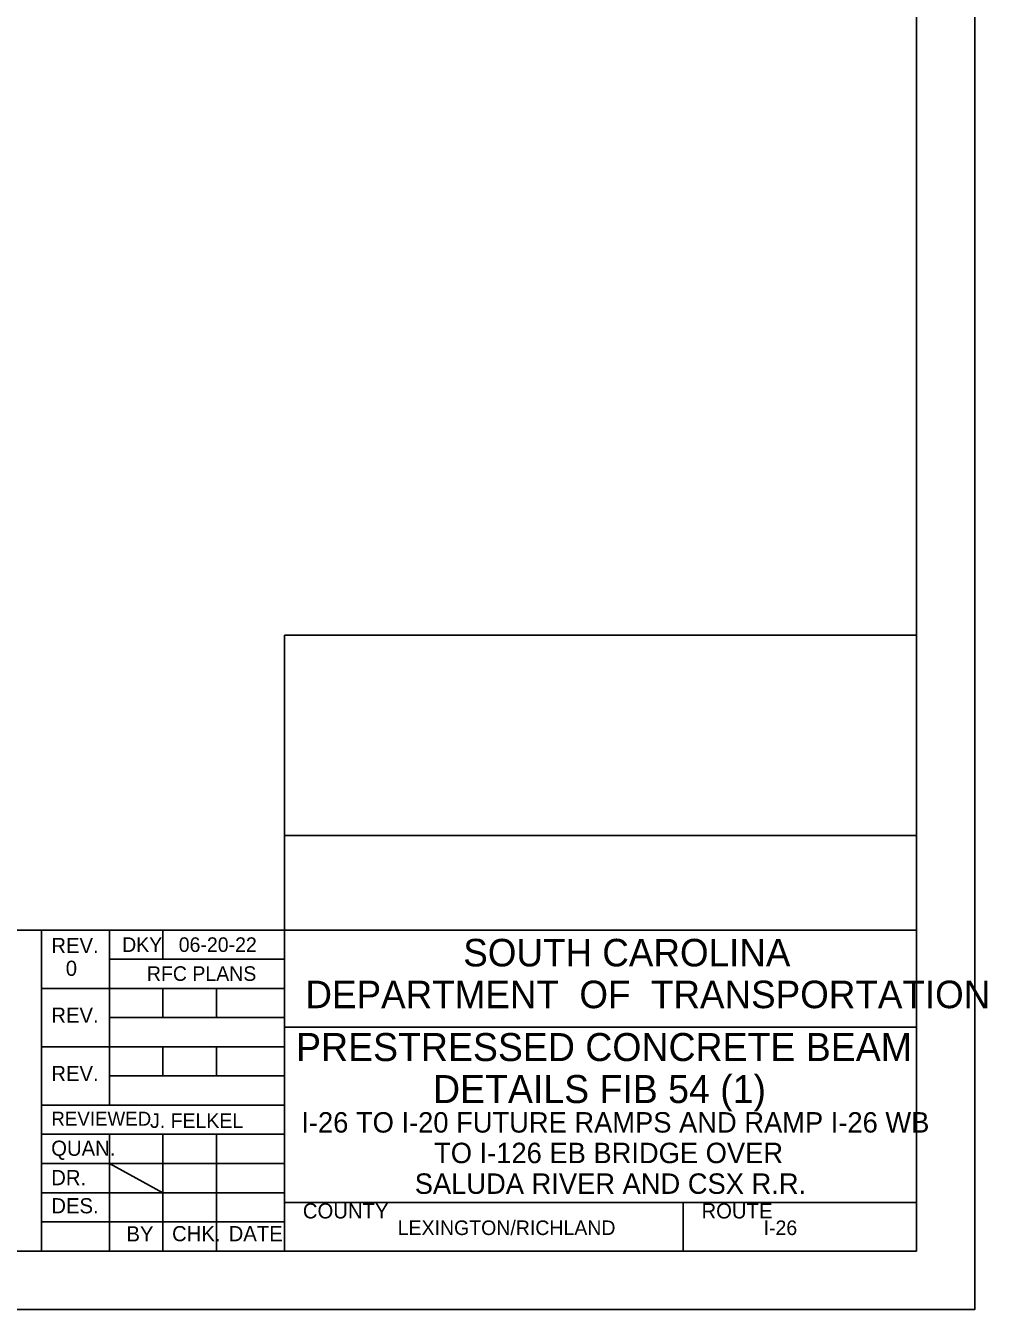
# Model space of a CAD drawing. Extents: x -55.6 to -19.5, y -5.1 to 16.9.
# Drawn here: x -27.72 to -19.48, y -5.09 to 5.91 of the extents above; entities that cross this region are included whole.
import ezdxf

# ---------------------------------------------------------------- set-up
doc = ezdxf.new("R2010")
doc.units = 0
for name, color, linetype in [('BR_BORDER LINES', 7, 'Continuous'), ('BR_TEXT', 7, 'Continuous'), ('Level 31', 7, 'Continuous')]:
    doc.layers.add(name, color=color, linetype=linetype)

msp = doc.modelspace()

# ---------------------------------------------------------------- linework, layer by layer
at = {"layer": 'BR_BORDER LINES'}
for p, q in [((-20.084, -4.592), (-20.084, 16.408)), ((-25.501, -4.592), (-25.501, 0.685)), ((-25.501, 0.685), (-20.084, 0.685)), ((-25.501, -1.03), (-20.084, -1.03)), ((-32.95, -1.842), (-27.584, -1.842)), ((-27.584, -4.592), (-27.584, -1.842)), ((-27.584, -1.842), (-20.084, -1.842)), ((-27.001, -1.842), (-27.001, -3.342)), ((-26.543, -2.092), (-26.543, -1.842)), ((-27.001, -2.092), (-25.501, -2.092)), ((-27.584, -2.342), (-25.501, -2.342)), ((-26.543, -2.592), (-26.543, -2.342)), ((-26.084, -2.592), (-26.084, -2.342)), ((-27.001, -2.592), (-25.501, -2.592)), ((-25.501, -2.675), (-25.501, -2.675)), ((-25.501, -2.675), (-20.084, -2.675)), ((-27.584, -2.842), (-25.501, -2.842)), ((-26.543, -3.092), (-26.543, -2.842)), ((-26.084, -3.092), (-26.084, -2.842)), ((-27.001, -3.092), (-25.501, -3.092)), ((-27.584, -3.342), (-25.501, -3.342)), ((-27.584, -3.592), (-25.501, -3.592)), ((-27.001, -3.592), (-27.001, -4.592)), ((-26.543, -3.592), (-26.543, -4.592)), ((-26.084, -3.592), (-26.084, -4.592)), ((-27.584, -3.842), (-25.501, -3.842)), ((-27.584, -4.092), (-25.501, -4.092)), ((-25.501, -4.175), (-20.084, -4.175)), ((-25.403, -4.175), (-20.084, -4.175)), ((-22.084, -4.592), (-22.084, -4.175)), ((-27.584, -4.342), (-25.501, -4.342)), ((-53.75, -4.592), (-20.084, -4.592))]:
    msp.add_line(p, q, dxfattribs=at)
at = {"layer": 'Level 31'}
for p, q in [((-22.792, -3.115), (-22.792, -3.115)), ((-27.001, -3.842), (-26.543, -4.092))]:
    msp.add_line(p, q, dxfattribs=at)
msp.add_lwpolyline([(-55.583, -5.092), (-19.583, -5.092), (-19.583, 16.908), (-55.583, 16.908)], close=True, dxfattribs=at)

# ---------------------------------------------------------------- texts
at = {"layer": 'BR_TEXT'}
for s, height, p in [('REV.', 0.13, (-27.5, -2.039)), ('DKY', 0.125, (-26.893, -2.029)), ('06-20-22', 0.125, (-26.408, -2.029)), ('SOUTH CAROLINA', 0.23587, (-23.969, -2.153)), ('0', 0.13, (-27.376, -2.234)), ('RFC PLANS', 0.125, (-26.681, -2.277)), ('DEPARTMENT  OF  TRANSPORTATION', 0.23587, (-25.322, -2.511)), ('REV.', 0.13, (-27.5, -2.636)), ('PRESTRESSED CONCRETE BEAM', 0.24, (-25.402, -2.964)), ('REV.', 0.13, (-27.5, -3.136)), ('DETAILS FIB 54 (1)', 0.24, (-24.228, -3.324)), ('REVIEWED', 0.12, (-27.5, -3.518)), ('I-26 TO I-20 FUTURE RAMPS AND RAMP I-26 WB', 0.175, (-25.357, -3.577)), ('J. FELKEL', 0.125, (-26.654, -3.537)), ('QUAN.', 0.13, (-27.501, -3.776)), ('TO I-126 EB BRIDGE OVER', 0.175, (-24.219, -3.839)), ('DR.', 0.13, (-27.501, -4.028)), ('SALUDA RIVER AND CSX R.R.', 0.175, (-24.385, -4.102)), ('DES.', 0.13, (-27.5, -4.269)), ('COUNTY', 0.13, (-25.344, -4.313)), ('ROUTE', 0.13, (-21.927, -4.313)), ('BY', 0.13, (-26.856, -4.51)), ('CHK.', 0.13, (-26.465, -4.508)), ('DATE', 0.13, (-25.98, -4.508)), ('LEXINGTON/RICHLAND', 0.12499, (-24.531, -4.455)), ('I-26', 0.125, (-21.395, -4.455))]:
    msp.add_text(s, height=height, dxfattribs=at).set_placement(p)

doc.saveas('drawing.dxf')
